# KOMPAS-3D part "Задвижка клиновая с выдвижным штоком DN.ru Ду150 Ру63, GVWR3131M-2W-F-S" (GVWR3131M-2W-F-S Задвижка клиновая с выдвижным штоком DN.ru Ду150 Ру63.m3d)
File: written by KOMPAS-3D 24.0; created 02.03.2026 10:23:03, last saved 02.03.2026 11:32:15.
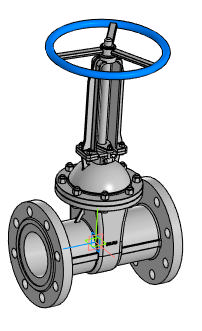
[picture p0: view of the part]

Document properties: Автор: R2D2; Полное имя файла: GVWR3131M-2W-F-S Задвижка клиновая с выдвижным штоком DN.ru Ду150 Ру63.cdw

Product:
- Part/product: Задвижка клиновая с выдвижным штоком DN.ru Ду150 Ру63  | designation GVWR3131M-2W-F-S
    Масса: 139
    Раздел спецификации: Прочие изделия
    Форматы листов документа: A2
    Примечание: D040-07396
    additional columns: D040-07396

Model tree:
1. Операция без истории:2

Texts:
  GVWR3131M-2W-F-S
